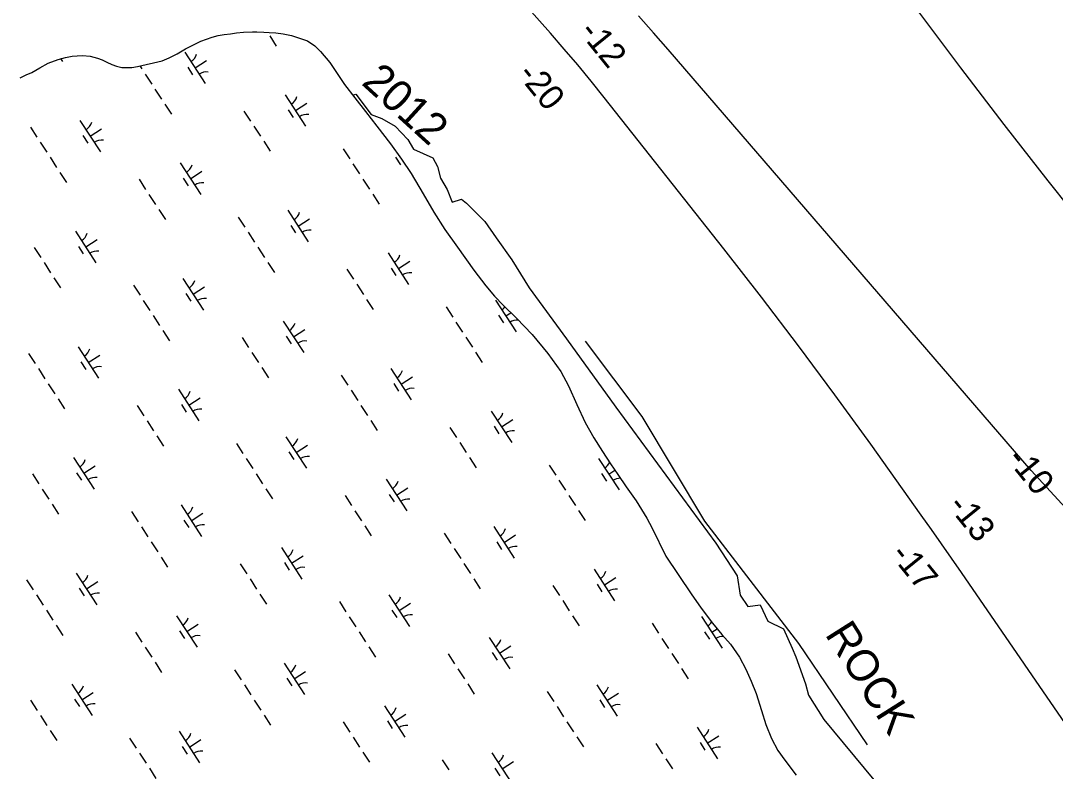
# Model space of a CAD drawing. Extents: x 3953924 to 3974542, y 193747 to 216192.
# Drawn here: x 3964005 to 3965380, y 202090 to 203089 of the extents above; entities that cross this region are included whole.
import ezdxf

# ---------------------------------------------------------------- set-up
doc = ezdxf.new("R2010")
doc.units = 0
for name, color, linetype in [('V-RIVR-EDGE', 7, 'Continuous'), ('V-RIVR-IDEN', 7, 'Continuous'), ('V-RIVR-JETY', 7, 'Continuous'), ('V-RIVR-RANG', 7, 'Continuous'), ('V-TOPO-MINR', 7, 'Continuous'), ('V-TOPO-SHOR', 7, 'Continuous'), ('V-WETL-SWMP', 7, 'Continuous')]:
    doc.layers.add(name, color=color, linetype=linetype)

msp = doc.modelspace()

# ---------------------------------------------------------------- linework, layer by layer
at = {"layer": 'V-RIVR-EDGE'}
msp.add_lwpolyline([(3964446.1, 202989.6), (3964450, 202990.6), (3964470.5, 202963.7), (3964484.6, 202958.6), (3964502.5, 202948.3), (3964519.2, 202930.4), (3964526.8, 202917.6), (3964552.5, 202906.1), (3964558.9, 202894.5), (3964562.7, 202879.2), (3964571.7, 202863.8), (3964578.1, 202847.1), (3964590.9, 202851), (3964597.3, 202845.9), (3964621.6, 202821.5), (3964637, 202799.8), (3964657.5, 202770.3), (3964680.5, 202733.2), (3964730.5, 202665.3), (3964795.8, 202574.4), (3964929, 202393.8), (3964957.1, 202350.3), (3964961, 202324.6), (3964971.2, 202309.3), (3964987.9, 202311.8), (3964998.1, 202290.1), (3965018.6, 202279.8), (3965030.1, 202254.2), (3965035.3, 202242.7), (3965048.1, 202206.8), (3965051.9, 202191.5), (3965072.4, 202159.4), (3965139, 202078.8)], dxfattribs=at)
at = {"layer": 'V-RIVR-JETY'}
msp.add_lwpolyline([(3964754.9, 202662.2), (3964830.3, 202562), (3964913.6, 202423.1), (3965038.6, 202260.5), (3965129.8, 202125.6)], dxfattribs=at)
at = {"layer": 'V-TOPO-MINR'}
for points in [[(3965506.6, 201988.8), (3965255.4, 202354.7), (3965242.2, 202373.9), (3965228.9, 202393), (3965215.5, 202412), (3965202, 202431), (3965134.7, 202525.3), (3965087, 202591), (3965038.7, 202656.3), (3964989.5, 202720.9), (3964939.6, 202785), (3964780.4, 202986.5), (3964763, 203008.2), (3964745.4, 203029.6), (3964727.4, 203050.8), (3964709.1, 203071.7), (3964596.1, 203199.1), (3964544.6, 203255.3), (3964491.9, 203310.5), (3964437.5, 203364), (3964382, 203416.4), (3964269.3, 203519.5)], [(3966027, 202084.7), (3965859.3, 202283.9), (3965807.6, 202345.4), (3965755.9, 202406.9), (3965704.3, 202468.4), (3965652.7, 202529.9), (3965575.8, 202621.6), (3965562.7, 202637.4), (3965549.7, 202653.1), (3965536.7, 202669), (3965523.8, 202684.9), (3965430.1, 202801.1), (3965370.8, 202875.5), (3965312.1, 202950.4), (3965254.4, 203026), (3965197.2, 203102.1)], [(3966314.9, 201388.7), (3966287.3, 201420.2), (3966260.1, 201452), (3966233.1, 201484), (3965904.6, 201876.4), (3965893.8, 201889.2), (3965883, 201901.9), (3965872.1, 201914.5), (3965861.1, 201927.1), (3965810.7, 201984.2), (3965774.3, 202025.2), (3965737.8, 202066), (3965701, 202106.6), (3965664, 202147), (3965348, 202490.2), (3964865.3, 203050), (3964845.8, 203072.5), (3964826.2, 203095)]]:
    msp.add_lwpolyline(points, dxfattribs=at)
at = {"layer": 'V-TOPO-SHOR'}
for points in [[(3964004.2, 203012.5), (3964012.1, 203016.3), (3964019.7, 203019.8), (3964030, 203025.9), (3964041.3, 203031.9), (3964054.4, 203037.1), (3964064.3, 203039.7), (3964073, 203041.3), (3964079.9, 203041.8), (3964087, 203042), (3964097, 203041.2), (3964107, 203038.8), (3964113.1, 203036.3), (3964119.4, 203033.4), (3964126, 203030.1), (3964132.2, 203027.9), (3964139.2, 203026.3), (3964145.3, 203026.2), (3964152.3, 203026.3), (3964160, 203027.6), (3964192.9, 203035.3), (3964202.1, 203039.2), (3964212.8, 203044.6), (3964223.7, 203050.9), (3964235.1, 203056.9), (3964244.3, 203061.2), (3964251.6, 203064), (3964259.1, 203066.6), (3964267, 203068.6), (3964275.1, 203070), (3964283.6, 203071.2), (3964291.7, 203072.2), (3964301.1, 203073.3), (3964312.7, 203073.6)], [(3964312.7, 203073.6), (3964318.4, 203073.6), (3964327.7, 203073.4), (3964335.2, 203073), (3964343.8, 203072.2), (3964353.5, 203070.9), (3964364.5, 203068.9), (3964385.8, 203061.5)]]:
    msp.add_lwpolyline(points, dxfattribs=at)
at = {"layer": 'V-WETL-SWMP'}
for p, q in [((3964267, 203068.6), (3964275.1, 203070)), ((3964275.1, 203070), (3964283.6, 203071.2)), ((3964283.6, 203071.2), (3964291.7, 203072.2)), ((3964291.7, 203072.2), (3964301.1, 203073.3)), ((3964301.1, 203073.3), (3964312.7, 203073.6)), ((3964312.7, 203073.6), (3964318.4, 203073.6)), ((3964318.4, 203073.6), (3964327.7, 203073.4)), ((3964327.7, 203073.4), (3964335.2, 203073)), ((3964335.2, 203073), (3964343.8, 203072.2)), ((3964343.8, 203072.2), (3964353.5, 203070.9)), ((3964353.5, 203070.9), (3964364.5, 203068.9)), ((3964223.7, 203050.9), (3964235.1, 203056.9)), ((3964235.1, 203056.9), (3964244.3, 203061.2)), ((3964244.3, 203061.2), (3964251.6, 203064)), ((3964251.6, 203064), (3964259.1, 203066.6)), ((3964259.1, 203066.6), (3964267, 203068.6)), ((3964335.7, 203068.2), (3964344.4, 203054.7)), ((3964364.5, 203068.9), (3964385.8, 203061.5)), ((3964385.8, 203061.5), (3964395.8, 203055.1)), ((3964202.1, 203039.2), (3964212.8, 203044.6)), ((3964212.8, 203044.6), (3964223.7, 203050.9)), ((3964222.8, 203046.7), (3964250.1, 203004.8)), ((3964395.8, 203055.1), (3964403.4, 203047.5)), ((3964403.4, 203047.5), (3964415.6, 203032.9)), ((3964030, 203025.9), (3964041.3, 203031.9)), ((3964041.3, 203031.9), (3964054.4, 203037.1)), ((3964054.4, 203037.1), (3964064.3, 203039.7)), ((3964057.7, 203038), (3964060.1, 203034.3)), ((3964064.3, 203039.7), (3964073, 203041.3)), ((3964073, 203041.3), (3964079.9, 203041.8)), ((3964079.9, 203041.8), (3964087, 203042)), ((3964087, 203042), (3964097, 203041.2)), ((3964097, 203041.2), (3964107, 203038.8)), ((3964107, 203038.8), (3964113.1, 203036.3)), ((3964113.1, 203036.3), (3964119.4, 203033.4)), ((3964119.4, 203033.4), (3964126, 203030.1)), ((3964126, 203030.1), (3964132.2, 203027.9)), ((3964160, 203027.6), (3964192.9, 203035.3)), ((3964192.9, 203035.3), (3964202.1, 203039.2)), ((3964236.5, 203025.7), (3964251.6, 203035.5)), ((3964415.6, 203032.9), (3964424.6, 203019.5)), ((3964004.2, 203012.5), (3964012.1, 203016.3)), ((3964012.1, 203016.3), (3964019.7, 203019.8)), ((3964019.7, 203019.8), (3964030, 203025.9)), ((3964132.2, 203027.9), (3964139.2, 203026.3)), ((3964139.2, 203026.3), (3964145.3, 203026.2)), ((3964145.3, 203026.2), (3964152.3, 203026.3)), ((3964152.3, 203026.3), (3964160, 203027.6)), ((3964163.2, 203028.3), (3964165.7, 203024.3)), ((3964170.1, 203017.6), (3964178.8, 203004.2)), ((3964226.7, 203026.5), (3964233.3, 203016.5)), ((3964424.6, 203019.5), (3964435.2, 203003.8)), ((3964435.2, 203003.8), (3964448.9, 202986)), ((3964183.2, 202997.5), (3964191.9, 202984.1)), ((3964356.3, 202990.1), (3964383.5, 202948.2)), ((3964196.3, 202977.4), (3964205, 202964)), ((3964369.9, 202969.1), (3964385, 202978.9)), ((3964448.9, 202986), (3964462.9, 202967.9)), ((3964301.5, 202968.4), (3964310.2, 202955)), ((3964360.2, 202969.9), (3964366.7, 202959.9)), ((3964462.9, 202967.9), (3964478.1, 202948.1)), ((3964017.6, 202947), (3964026.3, 202933.6)), ((3964083.4, 202955.9), (3964110.7, 202914)), ((3964314.6, 202948.3), (3964323.3, 202934.9)), ((3964478.1, 202948.1), (3964496.3, 202924.9)), ((3964087.3, 202935.8), (3964093.9, 202925.7)), ((3964097.1, 202935), (3964112.2, 202944.8)), ((3964030.7, 202926.9), (3964039.4, 202913.5)), ((3964327.7, 202928.2), (3964336.4, 202914.8)), ((3964496.3, 202924.9), (3964511, 202904.4)), ((3964043.8, 202906.8), (3964052.5, 202893.4)), ((3964433.3, 202918.2), (3964442.1, 202904.8)), ((3964503, 202907), (3964509.6, 202896.9)), ((3964216.9, 202899.3), (3964244.1, 202857.4)), ((3964446.4, 202898.1), (3964455.2, 202884.7)), ((3964511, 202904.4), (3964523.9, 202885.4)), ((3964056.9, 202886.7), (3964065.6, 202873.3)), ((3964162.1, 202877.6), (3964170.8, 202864.2)), ((3964220.8, 202879.2), (3964227.3, 202869.1)), ((3964230.5, 202878.4), (3964245.6, 202888.2)), ((3964459.5, 202877.9), (3964468.2, 202864.5)), ((3964523.9, 202885.4), (3964539.7, 202858.3)), ((3964175.2, 202857.5), (3964183.9, 202844.1)), ((3964472.6, 202857.8), (3964481.3, 202844.4)), ((3964539.7, 202858.3), (3964554, 202834)), ((3964188.3, 202837.4), (3964197, 202824)), ((3964359.7, 202836.4), (3964387, 202794.5)), ((3964293.9, 202827.4), (3964302.7, 202814)), ((3964373.4, 202815.4), (3964388.5, 202825.2)), ((3964554, 202834), (3964568.7, 202810.7)), ((3964077.5, 202808.6), (3964104.7, 202766.7)), ((3964363.6, 202816.2), (3964370.2, 202806.2)), ((3964568.7, 202810.7), (3964585.3, 202787.5)), ((3964091.1, 202787.6), (3964106.2, 202797.4)), ((3964307, 202807.3), (3964315.7, 202793.9)), ((3964022.7, 202786.9), (3964031.4, 202773.5)), ((3964081.4, 202788.4), (3964087.9, 202778.4)), ((3964320.1, 202787.2), (3964328.8, 202773.8)), ((3964585.3, 202787.5), (3964606.9, 202756.8)), ((3964333.2, 202767.1), (3964341.9, 202753.7)), ((3964493.2, 202779.7), (3964520.4, 202737.8)), ((3964506.8, 202758.8), (3964521.9, 202768.6)), ((3964035.8, 202766.8), (3964044.5, 202753.4)), ((3964438.4, 202758.1), (3964447.1, 202744.7)), ((3964497.1, 202759.6), (3964503.6, 202749.6)), ((3964606.9, 202756.8), (3964623.2, 202735.8)), ((3964048.9, 202746.7), (3964057.6, 202733.3)), ((3964220.3, 202745.6), (3964247.6, 202703.7)), ((3964154.5, 202736.7), (3964163.3, 202723.3)), ((3964234, 202724.7), (3964249.1, 202734.5)), ((3964451.5, 202738), (3964460.2, 202724.5)), ((3964623.2, 202735.8), (3964634.6, 202722)), ((3964167.6, 202716.6), (3964176.3, 202703.2)), ((3964224.2, 202725.5), (3964230.8, 202715.4)), ((3964464.6, 202717.8), (3964473.3, 202704.4)), ((3964634.6, 202722), (3964646, 202710.1)), ((3964636.1, 202716.8), (3964663.3, 202674.9)), ((3964570.2, 202707.9), (3964579, 202694.4)), ((3964646, 202710.1), (3964663.6, 202693.1)), ((3964649.7, 202695.8), (3964656.3, 202700.1)), ((3964180.7, 202696.5), (3964189.4, 202683)), ((3964353.8, 202689), (3964381, 202647.1)), ((3964583.3, 202687.7), (3964592.1, 202674.3)), ((3964640, 202696.7), (3964646.5, 202686.6)), ((3964663.6, 202693.1), (3964684.5, 202671.3)), ((3964193.8, 202676.3), (3964202.5, 202662.9)), ((3964367.4, 202668), (3964382.5, 202677.9)), ((3964684.5, 202671.3), (3964705.4, 202646)), ((3964299, 202667.3), (3964307.7, 202653.9)), ((3964357.7, 202668.9), (3964364.2, 202658.8)), ((3964596.4, 202667.6), (3964605.2, 202654.2)), ((3964015.1, 202645.9), (3964023.8, 202632.5)), ((3964080.9, 202654.9), (3964108.2, 202613)), ((3964094.6, 202633.9), (3964109.7, 202643.7)), ((3964312.1, 202647.2), (3964320.8, 202633.8)), ((3964609.5, 202647.5), (3964618.2, 202634.1)), ((3964705.4, 202646), (3964722.8, 202622)), ((3964084.8, 202634.7), (3964091.4, 202624.7)), ((3964028.2, 202625.8), (3964036.9, 202612.4)), ((3964325.2, 202627.1), (3964333.9, 202613.7)), ((3964430.8, 202617.1), (3964439.6, 202603.7)), ((3964496.7, 202626), (3964523.9, 202584.1)), ((3964722.8, 202622), (3964732.9, 202603.1)), ((3964041.3, 202605.7), (3964050, 202592.3)), ((3964500.6, 202605.9), (3964507.1, 202595.9)), ((3964510.3, 202605.1), (3964525.4, 202614.9)), ((3964732.9, 202603.1), (3964744.1, 202578)), ((3964214.4, 202598.3), (3964241.6, 202556.4)), ((3964443.9, 202597), (3964452.7, 202583.6)), ((3964054.4, 202585.6), (3964063.1, 202572.2)), ((3964159.6, 202576.6), (3964168.3, 202563.2)), ((3964218.3, 202578.1), (3964224.8, 202568.1)), ((3964228, 202577.3), (3964243.1, 202587.1)), ((3964457, 202576.9), (3964465.7, 202563.5)), ((3964744.1, 202578), (3964754.9, 202554.1)), ((3964630.1, 202569.4), (3964657.4, 202527.5)), ((3964172.7, 202556.5), (3964181.4, 202543.1)), ((3964470.1, 202556.8), (3964478.8, 202543.4)), ((3964575.3, 202547.7), (3964584, 202534.3)), ((3964634, 202549.3), (3964640.5, 202539.2)), ((3964643.7, 202548.5), (3964658.8, 202558.3)), ((3964754.9, 202554.1), (3964766.6, 202533.7)), ((3964185.8, 202536.4), (3964194.5, 202522.9)), ((3964357.2, 202535.3), (3964384.5, 202493.4)), ((3964766.6, 202533.7), (3964778.3, 202515.6)), ((3964291.4, 202526.4), (3964300.2, 202513)), ((3964370.9, 202514.3), (3964386, 202524.2)), ((3964588.4, 202527.6), (3964597.1, 202514.2)), ((3964075, 202507.5), (3964102.2, 202465.6)), ((3964304.5, 202506.3), (3964313.3, 202492.8)), ((3964361.1, 202515.2), (3964367.7, 202505.1)), ((3964601.5, 202507.5), (3964610.2, 202494.1)), ((3964773, 202506.5), (3964800.2, 202464.6)), ((3964778.3, 202515.6), (3964788.8, 202499.4)), ((3964088.6, 202486.6), (3964103.7, 202496.4)), ((3964707.1, 202497.5), (3964715.9, 202484.1)), ((3964788.8, 202499.4), (3964798.7, 202484.9)), ((3964020.2, 202485.8), (3964028.9, 202472.4)), ((3964078.9, 202487.4), (3964085.4, 202477.3)), ((3964317.6, 202486.1), (3964326.3, 202472.7)), ((3964490.7, 202478.7), (3964517.9, 202436.8)), ((3964776.9, 202486.3), (3964783.4, 202476.3)), ((3964786.6, 202485.5), (3964794.7, 202490.8)), ((3964798.7, 202484.9), (3964809.6, 202468.7)), ((3964033.3, 202465.7), (3964042, 202452.3)), ((3964330.7, 202466), (3964339.4, 202452.6)), ((3964504.3, 202457.7), (3964519.4, 202467.5)), ((3964720.2, 202477.4), (3964729, 202464)), ((3964809.6, 202468.7), (3964822.8, 202449.8)), ((3964435.9, 202457), (3964444.6, 202443.6)), ((3964494.6, 202458.5), (3964501.1, 202448.5)), ((3964733.3, 202457.3), (3964742.1, 202443.9)), ((3964046.4, 202445.6), (3964055.1, 202432.2)), ((3964217.8, 202444.6), (3964245.1, 202402.6)), ((3964746.4, 202437.2), (3964755.2, 202423.8)), ((3964822.8, 202449.8), (3964837.2, 202427)), ((3964152, 202435.6), (3964160.8, 202422.2)), ((3964221.7, 202424.4), (3964228.3, 202414.4)), ((3964231.5, 202423.6), (3964246.6, 202433.4)), ((3964449, 202436.9), (3964457.7, 202423.5)), ((3964837.2, 202427), (3964844.3, 202413.6)), ((3964165.1, 202415.5), (3964173.8, 202402.1)), ((3964462.1, 202416.8), (3964470.8, 202403.4)), ((3964633.6, 202415.7), (3964660.8, 202373.8)), ((3964844.3, 202413.6), (3964862.2, 202376.4)), ((3964567.7, 202406.8), (3964576.5, 202393.4)), ((3964647.2, 202394.8), (3964662.3, 202404.6)), ((3964178.2, 202395.4), (3964186.9, 202382)), ((3964351.3, 202387.9), (3964378.5, 202346)), ((3964580.8, 202386.7), (3964589.6, 202373.3)), ((3964637.5, 202395.6), (3964644, 202385.5)), ((3964191.3, 202375.3), (3964200, 202361.9)), ((3964364.9, 202367), (3964380, 202376.8)), ((3964862.2, 202376.4), (3964895.9, 202326.4)), ((3964296.5, 202366.3), (3964305.2, 202352.8)), ((3964355.2, 202367.8), (3964361.7, 202357.7)), ((3964593.9, 202366.6), (3964602.7, 202353.2)), ((3964767, 202359.1), (3964794.3, 202317.2)), ((3964012.6, 202344.9), (3964021.3, 202331.5)), ((3964078.4, 202353.8), (3964105.7, 202311.9)), ((3964092.1, 202332.9), (3964107.2, 202342.7)), ((3964309.6, 202346.1), (3964318.3, 202332.7)), ((3964607, 202346.4), (3964615.7, 202333)), ((3964780.6, 202338.2), (3964795.7, 202348)), ((3964082.3, 202333.7), (3964088.9, 202323.6)), ((3964712.2, 202337.4), (3964721, 202324)), ((3964770.9, 202339), (3964777.4, 202328.9)), ((3964025.7, 202324.8), (3964034.4, 202311.4)), ((3964322.7, 202326), (3964331.4, 202312.6)), ((3964428.3, 202316), (3964437.1, 202302.6)), ((3964494.2, 202325), (3964521.4, 202283.1)), ((3964507.8, 202304), (3964522.9, 202313.8)), ((3964725.3, 202317.3), (3964734, 202303.9)), ((3964895.9, 202326.4), (3964909.1, 202307.4)), ((3964038.8, 202304.6), (3964047.5, 202291.2)), ((3964498.1, 202304.8), (3964504.6, 202294.8)), ((3964909.1, 202307.4), (3964924.2, 202287.3)), ((3964211.9, 202297.2), (3964239.1, 202255.3)), ((3964225.5, 202276.2), (3964240.6, 202286.1)), ((3964441.4, 202295.9), (3964450.2, 202282.5)), ((3964738.4, 202297.2), (3964747.1, 202283.8)), ((3964844.1, 202287.2), (3964852.8, 202273.8)), ((3964909.9, 202296.1), (3964937.1, 202254.2)), ((3964924.2, 202287.3), (3964936.8, 202272.3)), ((3964051.9, 202284.5), (3964060.6, 202271.1)), ((3964157.1, 202275.5), (3964165.8, 202262.1)), ((3964215.8, 202277.1), (3964222.3, 202267)), ((3964454.5, 202275.8), (3964463.2, 202262.4)), ((3964913.8, 202276), (3964920.3, 202266)), ((3964923.5, 202275.2), (3964930.5, 202279.8)), ((3964936.8, 202272.3), (3964948.2, 202259.3)), ((3964627.6, 202268.4), (3964654.9, 202226.5)), ((3964857.1, 202267.1), (3964865.9, 202253.7)), ((3964948.2, 202259.3), (3964960.3, 202242.3)), ((3964170.2, 202255.4), (3964178.9, 202242)), ((3964467.6, 202255.7), (3964476.3, 202242.3)), ((3964572.8, 202246.7), (3964581.5, 202233.3)), ((3964631.5, 202248.2), (3964638, 202238.2)), ((3964641.2, 202247.4), (3964656.3, 202257.2)), ((3964870.2, 202247), (3964879, 202233.6)), ((3964183.3, 202235.3), (3964192, 202221.9)), ((3964354.8, 202234.2), (3964382, 202192.3)), ((3964960.3, 202242.3), (3964968.9, 202226.2)), ((3964288.9, 202225.3), (3964297.7, 202211.9)), ((3964368.4, 202213.3), (3964383.5, 202223.1)), ((3964585.9, 202226.6), (3964594.6, 202213.2)), ((3964883.3, 202226.9), (3964892.1, 202213.5)), ((3964968.9, 202226.2), (3964976, 202210.1)), ((3964072.5, 202206.4), (3964099.7, 202164.5)), ((3964302, 202205.2), (3964310.8, 202191.8)), ((3964358.6, 202214.1), (3964365.2, 202204)), ((3964599, 202206.5), (3964607.7, 202193)), ((3964770.5, 202205.4), (3964797.7, 202163.5)), ((3964976, 202210.1), (3964982.3, 202193.7)), ((3964086.1, 202185.5), (3964101.2, 202195.3)), ((3964704.6, 202196.5), (3964713.4, 202183.1)), ((3964784.1, 202184.4), (3964799.2, 202194.3)), ((3964982.3, 202193.7), (3964989.6, 202171.4)), ((3964017.7, 202184.8), (3964026.4, 202171.4)), ((3964076.4, 202186.3), (3964082.9, 202176.3)), ((3964315.1, 202185.1), (3964323.8, 202171.7)), ((3964488.2, 202177.6), (3964515.4, 202135.7)), ((3964717.7, 202176.4), (3964726.5, 202162.9)), ((3964774.4, 202185.3), (3964780.9, 202175.2)), ((3964030.8, 202164.7), (3964039.5, 202151.2)), ((3964328.2, 202165), (3964336.9, 202151.5)), ((3964501.8, 202156.7), (3964516.9, 202166.5)), ((3964989.6, 202171.4), (3964995.5, 202152.6)), ((3964433.4, 202155.9), (3964442.1, 202142.5)), ((3964492.1, 202157.5), (3964498.6, 202147.4)), ((3964730.8, 202156.2), (3964739.6, 202142.8)), ((3964903.9, 202148.8), (3964931.2, 202106.9)), ((3964995.5, 202152.6), (3965002.9, 202133.8)), ((3964043.9, 202144.5), (3964052.6, 202131.1)), ((3964149.5, 202134.6), (3964158.3, 202121.1)), ((3964215.3, 202143.5), (3964242.6, 202101.6)), ((3964446.5, 202135.8), (3964455.2, 202122.4)), ((3964743.9, 202136.1), (3964752.7, 202122.7)), ((3964917.5, 202127.8), (3964932.6, 202137.7)), ((3964219.2, 202123.4), (3964225.8, 202113.3)), ((3964229, 202122.5), (3964244.1, 202132.4)), ((3964849.1, 202127.1), (3964857.9, 202113.7)), ((3964907.8, 202128.7), (3964914.3, 202118.6)), ((3965002.9, 202133.8), (3965011.1, 202118.1)), ((3964162.6, 202114.4), (3964171.3, 202101)), ((3964459.6, 202115.7), (3964468.3, 202102.3)), ((3964631.1, 202114.7), (3964658.3, 202072.8)), ((3964862.2, 202107), (3964871, 202093.6)), ((3965011.1, 202118.1), (3965020.6, 202105.1)), ((3964175.7, 202094.3), (3964184.4, 202080.9)), ((3964565.2, 202105.7), (3964574, 202092.3)), ((3964635, 202094.5), (3964641.5, 202084.5)), ((3964644.7, 202093.7), (3964659.8, 202103.5)), ((3965020.6, 202105.1), (3965035.4, 202085.4))]:
    msp.add_line(p, q, dxfattribs=at)
for centre, start, end in [((3964221.6, 203049), 302.2901, 343.8338), ((3964251.7, 203002.7), 82.2901, 123.8337), ((3964355, 202992.4), 302.2901, 343.8338), ((3964385.2, 202946.1), 82.2901, 123.8337), ((3964082.2, 202958.3), 302.2901, 343.8338), ((3964112.3, 202912), 82.2901, 123.8337), ((3964215.6, 202901.6), 302.2901, 343.8338), ((3964245.8, 202855.3), 82.2901, 123.8337), ((3964358.5, 202838.7), 302.2901, 343.8338), ((3964388.7, 202792.4), 82.2901, 123.8337), ((3964076.2, 202810.9), 302.2901, 343.8338), ((3964106.4, 202764.6), 82.2901, 123.8337), ((3964491.9, 202782.1), 302.2901, 343.8338), ((3964522.1, 202735.8), 82.2901, 123.8337), ((3964219.1, 202747.9), 302.2901, 343.8338), ((3964249.2, 202701.6), 82.2901, 123.8337), ((3964634.8, 202719.1), 302.2901, 320.214), ((3964352.5, 202691.3), 302.2901, 343.8338), ((3964665, 202672.8), 86.2015, 123.8337), ((3964382.7, 202645), 82.2901, 123.8337), ((3964079.7, 202657.2), 302.2901, 343.8338), ((3964109.8, 202610.9), 82.2901, 123.8337), ((3964495.4, 202628.4), 302.2901, 343.8338), ((3964213.1, 202600.6), 302.2901, 343.8338), ((3964525.6, 202582.1), 82.2901, 123.8337), ((3964243.3, 202554.3), 82.2901, 123.8337), ((3964628.8, 202571.8), 302.2901, 343.8338), ((3964659, 202525.5), 82.2901, 123.8337), ((3964356, 202537.6), 302.2901, 343.8338), ((3964386.2, 202491.3), 82.2901, 123.8337), ((3964073.7, 202509.8), 302.2901, 343.8338), ((3964771.7, 202508.8), 302.2901, 334.6045), ((3964103.9, 202463.5), 82.2901, 123.8337), ((3964801.9, 202462.5), 89.9839, 123.8337), ((3964489.4, 202481), 302.2901, 343.8338), ((3964519.6, 202434.7), 82.2901, 123.8337), ((3964216.6, 202446.9), 302.2901, 343.8338), ((3964246.8, 202400.6), 82.2901, 123.8337), ((3964632.3, 202418), 302.2901, 343.8338), ((3964350, 202390.3), 302.2901, 343.8338), ((3964662.5, 202371.8), 82.2901, 123.8337), ((3964380.2, 202344), 82.2901, 123.8337), ((3964765.7, 202361.4), 302.2901, 343.8338), ((3964077.2, 202356.1), 302.2901, 343.8338), ((3964107.3, 202309.8), 82.2901, 123.8337), ((3964795.9, 202315.1), 82.2901, 123.8337), ((3964492.9, 202327.3), 302.2901, 343.8338), ((3964210.6, 202299.5), 302.2901, 343.8338), ((3964523.1, 202281), 82.2901, 123.8337), ((3964908.6, 202298.5), 302.2901, 326.0656), ((3964240.8, 202253.2), 82.2901, 123.8337), ((3964626.3, 202270.7), 302.2901, 343.8338), ((3964938.8, 202252.2), 89.3335, 123.8337), ((3964353.5, 202236.6), 302.2901, 343.8338), ((3964656.5, 202224.4), 82.2901, 123.8337), ((3964071.2, 202208.8), 302.2901, 343.8338), ((3964383.7, 202190.3), 82.2901, 123.8337), ((3964769.2, 202207.7), 302.2901, 343.8338), ((3964101.4, 202162.5), 82.2901, 123.8337), ((3964799.4, 202161.4), 82.2901, 123.8337), ((3964486.9, 202179.9), 302.2901, 343.8338), ((3964517.1, 202133.6), 82.2901, 123.8337), ((3964214.1, 202145.8), 302.2901, 343.8338), ((3964902.7, 202151.1), 302.2901, 343.8338), ((3964932.8, 202104.8), 82.2901, 123.8337), ((3964244.3, 202099.5), 82.2901, 123.8337), ((3964629.8, 202117), 302.2901, 343.8338)]:
    msp.add_arc(centre, 17.6, start, end, dxfattribs=at)

# ---------------------------------------------------------------- texts
at = {"layer": 'V-RIVR-IDEN'}
for s, rotation, p in [('2012', 317.642, (3964456.4, 203004.7)), ('ROCK', 302.3552, (3965073.1, 202272.6))]:
    msp.add_text(s, height=42, rotation=rotation, dxfattribs=at).set_placement(p)
at = {"layer": 'V-RIVR-RANG'}
for s, rotation, p in [('-12', 308.9424, (3964745.9, 203073.3)), ('-20', 308.9424, (3964663.9, 203016.7)), ('-10', 309.0106, (3965314.4, 202505.1)), ('-13', 309.0106, (3965236, 202443)), ('-17', 309.0106, (3965159.8, 202378))]:
    msp.add_text(s, height=33.5, rotation=rotation, dxfattribs=at).set_placement(p)

doc.saveas('drawing.dxf')
